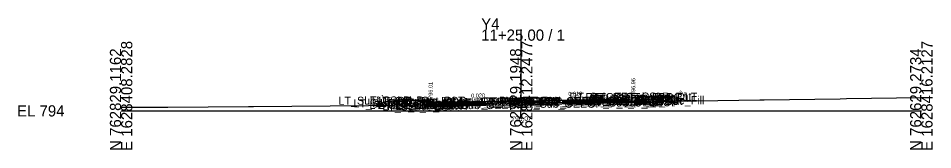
# Model space of a CAD drawing. Extents: x -26 to 203, y -10 to 3017.
# Drawn here: x -25.7 to 202.8, y 2490.3 to 2523.1 of the extents above; entities that cross this region are included whole.
import ezdxf

# ---------------------------------------------------------------- set-up
doc = ezdxf.new("R2010")
doc.units = 0
for name, color, linetype in [('Default', 7, 'Continuous'), ('Exist Cross Section Cell', 7, 'Continuous'), ('Exist XS Center Line Elevation Label', 7, 'Continuous'), ('Exist XS Ground Line', 7, 'Continuous'), ('Prop CMT Conc Surface', 7, 'Continuous'), ('Prop CMT Concrete Structures', 7, 'Continuous'), ('Prop CMT Pvmt Course 1', 7, 'Continuous'), ('Prop CMT Pvmt Course 1 CG', 7, 'Continuous'), ('Prop CMT Pvmt Course 2', 7, 'Continuous'), ('Prop CMT Pvmt Course 3', 7, 'Continuous'), ('Prop CMT Pvmt Surface', 7, 'Continuous'), ('Prop CMT Slope Grass', 7, 'Continuous'), ('Prop CMT Subgrade Earthwork', 7, 'Continuous'), ('Prop XS Hydro Elevations', 7, 'Continuous'), ('Prop XS SE Text', 7, 'Continuous'), ('Prop XS Side Slope Text', 7, 'Continuous'), ('Scratch_Level_0', 7, 'Continuous')]:
    doc.layers.add(name, color=color, linetype=linetype)

msp = doc.modelspace()

# ---------------------------------------------------------------- linework, layer by layer
at = {"layer": 'Exist Cross Section Cell'}
for p, q in [((100, 2500), (100, 2520.33)), ((0, 2500), (100, 2500)), ((100, 2500), (200, 2500))]:
    msp.add_line(p, q, dxfattribs=at)
at = {"layer": 'Exist XS Ground Line'}
msp.add_lwpolyline([(0, 2500.89), (9.57, 2500.96), (10.85, 2500.96), (11.7, 2500.97), (31.83, 2501.12), (33.12, 2501.13), (61.83, 2501.34), (74.53, 2501.48), (75.5, 2501.48), (79.22, 2501.5), (98.96, 2502.06), (100, 2502.07), (100.91, 2502.08), (118.94, 2502.09), (121, 2502.12), (124, 2502.17), (127.62, 2502.23), (131.67, 2502.3), (133.34, 2502.32), (159.66, 2502.74), (160.73, 2502.76), (179.68, 2503.05), (181.28, 2503.08), (200, 2503.38)], dxfattribs=at)
at = {"layer": 'Prop CMT Conc Surface'}
for points in [[(77.35, 2502.01), (77.34, 2502.51), (76.84, 2502.51)], [(126, 2503), (128, 2502.96)], [(128, 2502.96), (128.01, 2503.46), (128.51, 2503.46)], [(79.35, 2502.13), (77.35, 2502.01)]]:
    msp.add_lwpolyline(points, dxfattribs=at)
at = {"layer": 'Prop CMT Concrete Structures'}
for points in [[(79.35, 2502.13), (77.35, 2502.01), (77.34, 2502.51), (76.84, 2502.51)], [(76.84, 2502.51), (76.85, 2501.5), (79.35, 2501.55)], [(126, 2503), (128, 2502.96), (128.01, 2503.46), (128.51, 2503.46)], [(128.51, 2503.46), (128.5, 2502.46), (126, 2502.42)], [(126, 2502.42), (126, 2503)], [(132.51, 2503.54), (132.51, 2503.21)], [(132.51, 2503.21), (137.51, 2503.31)], [(137.51, 2503.31), (137.51, 2503.64)], [(79.35, 2501.55), (79.35, 2502.13)]]:
    msp.add_lwpolyline(points, dxfattribs=at)
at = {"layer": 'Prop CMT Pvmt Course 1'}
for points in [[(100, 2502.55), (79.35, 2502.13)], [(100, 2502.55), (126, 2503)], [(110.37, 2502.57), (100, 2502.42)], [(100, 2502.3), (100, 2502.55)], [(100, 2502.3), (100, 2502.55)], [(126, 2502.75), (110.37, 2502.44)], [(110.37, 2502.44), (110.37, 2502.57)], [(126, 2503), (126, 2502.75)], [(79.35, 2502.13), (79.35, 2501.88)], [(79.35, 2501.88), (91.13, 2502.12)], [(91.13, 2502.24), (100, 2502.42)], [(91.13, 2502.12), (91.13, 2502.24)], [(100, 2502.42), (100, 2502.3), (100, 2502.3)], [(100, 2502.42), (100, 2502.3), (100, 2502.3)]]:
    msp.add_lwpolyline(points, dxfattribs=at)
at = {"layer": 'Prop CMT Pvmt Course 1 CG'}
for points in [[(126, 2502.42), (129, 2502.47), (129.33, 2502.14)], [(79.35, 2501.55), (76.35, 2501.49), (76.01, 2501.15)], [(76.01, 2501.15), (79.35, 2501.22)], [(79.35, 2501.22), (79.35, 2501.55)], [(126, 2502.09), (126, 2502.42)], [(129.33, 2502.14), (126, 2502.09)]]:
    msp.add_lwpolyline(points, dxfattribs=at)
at = {"layer": 'Prop CMT Pvmt Course 2'}
for points in [[(110.37, 2502.44), (126, 2502.75)], [(110.37, 2502.11), (110.37, 2502.44)], [(126, 2502.75), (126, 2502.42)], [(91.13, 2502.12), (79.35, 2501.88)], [(79.35, 2501.88), (79.35, 2501.55)], [(79.35, 2501.55), (91.13, 2501.78)], [(91.13, 2501.78), (91.13, 2502.12)], [(126, 2502.42), (110.37, 2502.11)]]:
    msp.add_lwpolyline(points, dxfattribs=at)
at = {"layer": 'Prop CMT Pvmt Course 3'}
for points in [[(91.13, 2501.78), (79.35, 2501.55)], [(79.35, 2501.55), (79.35, 2501.22)], [(79.35, 2501.22), (91.13, 2501.45)], [(91.13, 2501.45), (91.13, 2501.78)], [(110.37, 2502.11), (126, 2502.42)], [(110.37, 2501.78), (110.37, 2502.11)], [(126, 2502.09), (110.37, 2501.78)], [(126, 2502.42), (126, 2502.09)]]:
    msp.add_lwpolyline(points, dxfattribs=at)
at = {"layer": 'Prop CMT Pvmt Surface'}
for points in [[(100, 2502.55), (79.35, 2502.13)], [(100, 2502.55), (126, 2503)]]:
    msp.add_lwpolyline(points, dxfattribs=at)
at = {"layer": 'Prop CMT Slope Grass'}
for points in [[(67.34, 2502.7), (63.31, 2501.36)], [(76.84, 2502.51), (67.34, 2502.7)], [(128.51, 2503.46), (138.01, 2503.65)], [(138.01, 2503.65), (141.59, 2502.45)]]:
    msp.add_lwpolyline(points, dxfattribs=at)
at = {"layer": 'Prop CMT Subgrade Earthwork'}
for points in [[(79.35, 2501.22), (76.01, 2501.15), (74.6, 2502.56)], [(126, 2502.09), (129.33, 2502.14), (130.69, 2503.5)], [(91.13, 2501.45), (79.35, 2501.22)], [(110.37, 2501.78), (126, 2502.09)]]:
    msp.add_lwpolyline(points, dxfattribs=at)

# ---------------------------------------------------------------- texts
at = {"layer": 'Default'}
msp.add_text('-', height=0.0001, dxfattribs=at).set_placement((0, 2500))
at = {"layer": 'Exist Cross Section Cell'}
for s, p in [('Y4', (90, 2520.33)), ('11+25.00 / 1', (90, 2517.53)), ('EL 794', (-26, 2498.6))]:
    msp.add_text(s, height=2.8, dxfattribs=at).set_placement(p)
for s, p in [('E 1628408.2828', (2.8, 2490)), ('E 1628412.2477', (102.8, 2490)), ('E 1628416.2127', (202.8, 2490)), ('N 762829.1162', (0, 2490)), ('N 762729.1948', (100, 2490)), ('N 762629.2734', (200, 2490))]:
    msp.add_text(s, height=2.8, rotation=90, dxfattribs=at).set_placement(p)
at = {"layer": 'Exist XS Center Line Elevation Label'}
msp.add_text('796.07', height=1.2, dxfattribs=at).set_placement((97.54, 2497.47))
at = {"layer": 'Prop XS Hydro Elevations'}
for s, p in [('796.01', (77.85, 2503.01)), ('796.96', (128.5, 2503.96))]:
    msp.add_text(s, height=1, rotation=90, dxfattribs=at).set_placement(p)
at = {"layer": 'Prop XS SE Text'}
for s, rotation, p in [('0.018', 1.0119, (111.79, 2503.75)), ('0.020', 1.1458, (87.5, 2503.3))]:
    msp.add_text(s, height=1, rotation=rotation, dxfattribs=at).set_placement(p)
at = {"layer": 'Prop XS Side Slope Text'}
for rotation, p in [(341.5651, (139.21, 2504.18)), (18.4349, (64.14, 2502.55))]:
    msp.add_text('3:1', height=1, rotation=rotation, dxfattribs=at).set_placement(p)
at = {"layer": 'Scratch_Level_0'}
for s, p in [('LT_Sub_Trench_Out_DLT', (54.35, 2501.54)), ('LT_Slope_Fill', (58.08, 2500.86)), ('LT_CSLP_Pnt', (60.71, 2501.61)), ('LT_CG1_Shelf_Out', (62.09, 2500.47)), ('LT_CG_Top_Face', (63.79, 2501.5)), ('LT_CG_Top_BOC', (64.32, 2501.5)), ('LT_CG_Bot_BOC', (64.35, 2500.48)), ('LT_CG_Top_Gut', (64.77, 2501)), ('LT_CG_Bot_IE', (68.45, 2500.53)), ('LT_PV2_OEOT', (68.71, 2500.87)), ('LT_PV3_OEOT', (68.71, 2500.53)), ('LT_PV1_OEOT', (69.27, 2501.12)), ('LT_Sub_OEEOP', (80.34, 2500.45)), ('LT_PV2_OEEOP', (80.44, 2501.12)), ('LT_PV3_OEEOP', (80.44, 2500.78)), ('LT_PV1_OEEOP', (81, 2501.24)), ('RT_PV2_IEEOP', (89.91, 2501.3)), ('LT_PV2_IEEOP', (89.95, 2501.3)), ('RT_PV1_IEEOP', (90.47, 2501.42)), ('LT_PV1_IEEOP', (90.52, 2501.42)), ('PV2_PGL', (93.91, 2501.3)), ('PV1_PGL', (94.47, 2501.55)), ('RT_Sub_OEEOP', (99.54, 2500.78)), ('RT_PV2_OEEOP', (99.63, 2501.44)), ('RT_PV3_OEEOP', (99.63, 2501.11)), ('RT_PV1_OEEOP', (100.2, 2501.57)), ('RT_Sub_Trench_Out_DLT', (112.07, 2502.52)), ('RT_CG_Top_Face', (116.07, 2502.47)), ('RT_CG1_Shelf_Out', (116.37, 2501.49)), ('RT_CG_Bot_IE', (116.73, 2501.44)), ('RT_Sub_OEOT', (116.89, 2501.1)), ('RT_PV2_OEOT', (116.99, 2501.77)), ('RT_PV3_OEOT', (116.99, 2501.44)), ('RT_CG_Top_Gut', (117.05, 2501.97)), ('RT_PV1_OEOT', (117.55, 2502.02)), ('RT_CG_Top_BOC', (117.6, 2502.47)), ('RT_CG_Bot_BOC', (117.63, 2501.48)), ('RT_Sub_OEOP', (120.25, 2501.16)), ('RT_CSLP_Pnt', (124.99, 2502.58)), ('RT_Slope_Fill', (128.96, 2501.68)), ('LT_Sub_OEOP', (65.3, 2500.13)), ('LT_Sub_OEOT', (68.61, 2500.2))]:
    msp.add_text(s, height=2, dxfattribs=at).set_placement(p)

doc.saveas('drawing.dxf')
